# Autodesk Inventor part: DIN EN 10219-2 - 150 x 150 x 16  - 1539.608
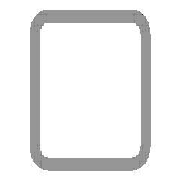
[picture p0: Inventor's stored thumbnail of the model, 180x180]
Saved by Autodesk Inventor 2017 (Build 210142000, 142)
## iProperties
Created: 2017-11
Part Number: DIN EN 10219-2 - 150 x 150 x 16  - 1539.608
Material: Steel, Mild
Description: Cold formed welded structural hollow sections of non-alloy and fine grain structural steel
Document SubType Name: Modeling
Standard: DIN
Designer: iusti
Standard Revision: 2006-07
Standards Organization: DIN
Language: en-US
Size Designation: 150 x 150 x 16
Categories: <MemberInstance><Categories><Category DisplayName="Structural Shapes" InternalName="089c4875-fa83-4c05-b084-43b9cc11f5ed" Mnemonic="GRDR"><CategoryParameter Dis
Stock Number: 150 x 150 x 16
Mass: 90369.3 g
Surface Area: 14539.6 cm^2
Volume: 11512 cm^3
Density: 7.85 g/cm^3
Appearance: Semi-Polished
IsCustomPart: 1
G_W: 150.000 mm
G_H: 150.000 mm
G_L: 1539.608 mm
+5BB57DF3-1F1E-4AEC-9498-ACD0E832ECA7+CUTDETAIL2: Cut
_CCFamilyMember: 76
_CCFamilyDisplayName: DIN EN 10219-2 (Square Hollow Section - Cold Formed) - Cold formed welded structural hollow sections of non-alloy and fine grain structural steel
_FrameMemberDoc: Frame Member File
_Version: 15.0.0
_GetPNFromCC: 1
Author: iusti
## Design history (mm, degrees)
node "Start plane"
node "End plane"
sketch "Sketch"
  geometry: L1 (-75, -27)-(-75, 27); L2 (-27, 75)-(27, 75); L3 (75, 27)-(75, -27); L4 (27, -75)-(-27, -75); L5 (-27, 59)-(27, 59); L6 (59, 27)-(59, -27); L7 (27, -59)-(-27, -59); L8 (-59, -27)-(-59, 27); L9 (0, 118.918)-(0, -118.918) reference; L10 (-118.918, 0)-(118.918, 0) reference; A1 r 48 centre (-27, -27) between (-75, -27) and (-27, -75); A2 r 48 centre (-27, 27) between (-27, 75) and (-75, 27); A3 r 48 centre (27, 27) between (75, 27) and (27, 75); A4 r 48 centre (27, -27) between (27, -75) and (75, -27); A5 r 32 centre (-27, 27) between (-27, 59) and (-59, 27); A6 r 32 centre (27, 27) between (59, 27) and (27, 59); A7 r 32 centre (27, -27) between (27, -59) and (59, -27); A8 r 32 centre (-27, -27) between (-59, -27) and (-27, -59)
  constraints: 16 end point, 16 point on circle, 8 centre point, 8 tangent, 4 parallel, 3 equal radius, 2 perpendicular, 7 other
  dimensions: "d7" = 48 radius of A1 (= G_IR); "d10" = 150 distance between parallel lines of L2 L4 (= G_H); "d11" = 150 distance between parallel lines of L1 L3 (= G_W); "d12" = 16 distance between parallel lines of L3 L6 (= G_T); "d15" = 75 distance between parallel lines of L2 L10 (= 0.5 x d10); "d16" = 75 distance between parallel lines of L9 L3 (= 0.5 x d11)
extrude "Body" new body sketch "Sketch" stored distance "d3" = 1539.60835 (= G_L); taper "d4" = 0 deg
node "Driven Length"
  sketch "Sketch3"
    geometry: L1 (0, 0)-(10, 0) reference
    constraints: 2 end point, 1 horizontal
  workplane "Work Plane3"
  sketch "Sketch4"
    geometry: L1 (-2, 0)-(12, 0) reference; L2 (-2, 1539.608)-(12, 1539.608) reference
    dimensions: "d18" = 1539.60835 distance between parallel lines of L1 L2 (derived)
workplane "Work Plane5"
split "Split2"
body "Solid1"
other parameters: "G_W" = 150 [user parameter; used in 1 equation term], "G_H" = 150 [user parameter; used in 1 equation term], "G_T" = 16 [user parameter; used in 1 equation term], "G_IR" = 48 [user parameter; used in 1 equation term], "G_L" = 1539.60835 (= d18) [user parameter; used in 1 equation term], "G_OFFSET_START" = 0 [user parameter; used in 1 equation term], "G_OFFSET_END" = -75 [user parameter; used in 1 equation term], "d13" = 0 (computed from G_OFFSET_START), "d14" = 1539.60835 (= G_OFFSET_END + B_L), "B_L" = 1614.60835 [user parameter; used in 1 equation term], "d17" = 90 deg
